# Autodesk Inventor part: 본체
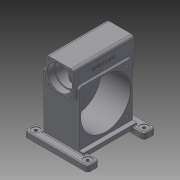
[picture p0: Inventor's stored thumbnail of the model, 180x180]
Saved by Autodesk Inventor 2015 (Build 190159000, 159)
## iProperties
Created: 2025-06
Part Number: 본체
Material: 일반
Document SubType Name: Modeling
Designer: 104
Density: 1 g/cm^3
Appearance: 기본값
Author: 104
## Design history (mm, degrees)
sketch "스케치1"
  geometry: L1 (-93, -103)-(93, -103); L2 (93, -103)-(93, 103); L3 (93, 103)-(-93, 103); L4 (-93, 103)-(-93, -103); L5 (-93, -103)-(93, 103); L6 (93, -103)-(-93, 103); 1 further point
  constraints: 12 end point, 2 midpoint, 2 parallel, 1 horizontal, 1 perpendicular
  dimensions: "d0" = 186 distance of L3.end L2.end; "d1" = 206 distance of L2.end L1.end
extrude "돌출1" new body sketch "스케치1" distance "d2" = 140; taper "d3" = 0 deg
sketch "스케치2"
  geometry: L1 (140, 206)-(125, 206); L2 (125, 206)-(125, 17); L3 (125, 17)-(140, 17); L4 (140, 17)-(140, 206); 1 further point
  constraints: 8 end point, 2 parallel, 1 horizontal, 1 perpendicular
  dimensions: "d4" = 15 distance of L3.end L2.end; "d5" = 189 distance of L2.end L1.end
extrude "돌출2" cut sketch "스케치2" stored distance "d6" = 140; taper "d7" = 0 deg
node "작업 평면1"
sketch "스케치3"
  geometry: L1 (-140, -86)-(-125, -86) reference; L2 (-125, -86)-(-125, 103) reference; L3 (0, 103)-(-125, 103) reference; L4 (0, 103)-(0, -103) reference; L5 (0, -103)-(-140, -103) reference; L6 (-140, -86)-(-140, -103) reference; L7 (-22, 158)-(-118, 158); L8 (-118, 158)-(-118, 62); L9 (-118, 62)-(-22, 62); L10 (-22, 62)-(-22, 158); 3 further points
  constraints: 8 end point, 2 midpoint, 2 parallel, 1 horizontal, 1 perpendicular, 1 vertical alignment
  dimensions: "d9" = 96 distance of L7.start L7.end; "d10" = 96 distance of L7.end L8.end; "d11" = 55 distance between parallel lines of L7 L3
extrude "돌출3" join sketch "스케치3" distance "d12" = 210; taper "d13" = 0 deg
sketch "스케치4"
  geometry: L1 (118, 62)-(22, 62) reference; L2 (118, 158)-(118, 62) reference; C1 r 42.5 at (70, 110); 3 further points
  constraints: 2 midpoint, 1 centre point, 1 horizontal alignment, 1 vertical alignment
  dimensions: "d14" = 85 diameter of C1
extrude "돌출4" cut sketch "스케치4" distance "d15" = 23; taper "d16" = 0 deg
sketch "스케치5"
  geometry: C1 r 42.5 at (0, 0) reference; C2 r 38.5 at (0, 0); 1 further point
  constraints: 1 centre point, 1 coincident
  dimensions: "d17" = 77 diameter of C2
extrude "돌출5" cut sketch "스케치5" stored distance "d18" = 23; taper "d19" = 0 deg
node "작업 평면2"
sketch "스케치7"
  geometry: L1 (158, -13)-(-62, -13); L2 (-62, -13)-(-62, 27); L3 (-62, 27)-(158, 27); L4 (158, 27)-(158, -13); L5 (96, 0)-(0, 0) reference; L6 (158, 223)-(-62, 223); L7 (-62, 223)-(-62, 183); L8 (-62, 183)-(158, 183); L9 (158, 183)-(158, 223); L10 (96, 210)-(0, 210) reference; 5 further points
  constraints: 16 end point, 4 midpoint, 4 parallel, 2 horizontal, 2 perpendicular, 2 vertical alignment
  dimensions: "d26" = 220 distance of L2.end L3.end; "d27" = 40 distance of L1.end L2.end; "d28" = 118 distance from line of L1 point (-22, 105); "d29" = 220 distance of L8.end L7.end; "d30" = 40 distance of L7.end L6.end; "d31" = 118 distance from line of L6 point (-22, 105)
extrude "돌출6" join sketch "스케치7" distance "d32" = 20; taper "d33" = 0 deg
sketch "스케치8"
  geometry: L1 (216, 171)-(216, 211) reference; C1 r 86 at (93, 93); 1 further point
  constraints: 1 centre point, 1 horizontal alignment
  dimensions: "d34" = 172 diameter of C1; "d35" = 123 distance from line of L1 C1.centre
extrude "돌출7" cut sketch "스케치8" distance "d36" = 102; taper "d37" = 0 deg
sketch "스케치9"
  geometry: C1 r 86 at (0, 0) reference; 1 further point
hole "구멍1" sketch "스케치9" at (0, 0) diameter "d38" = 62; stored, may be unused: countersink angle "d42" = 90 deg, drill point angle "d44" = 0 deg; dims "d39" = 6, "d40" = 4, "d41" = 2, "d43" = 16
sketch "스케치10"
  geometry: C1 r 31 at (0, 0) reference; 1 further point
hole "구멍2" sketch "스케치10" at (0, 0) diameter "d45" = 54; stored, may be unused: countersink angle "d49" = 90 deg, drill point angle "d51" = 0 deg; dims "d46" = 6, "d47" = 4, "d48" = 2, "d50" = 3
fillet "모깎기1" dims "d52" = 1
fillet "모깎기2" dims "d53" = 10
sketch "스케치11"
  geometry: L1 (148, 223)-(-52, 223) reference; L2 (-62, -3)-(-62, 17) reference; L3 (-52, 27)-(148, 27) reference; L4 (158, 17)-(158, -3) reference; L5 (148, -13)-(-52, -13) reference; L6 (-42, 7)-(138, 7); L7 (138, 7)-(138, 203); L8 (138, 203)-(-42, 203); L9 (-42, 203)-(-42, 7); L10 (148, -13)-(-52, -13) reference; L11 (48, -13)-(48, 223); A1 r 10 centre (-52, -3) between (-62, -3) and (-52, -13) reference; A2 r 10 centre (148, -3) between (148, -13) and (158, -3) reference; A3 r 10 centre (148, 17) between (158, 17) and (148, 27) reference; A4 r 10 centre (-52, 17) between (-52, 27) and (-62, 17) reference; 4 further points
  constraints: 10 end point, 5 midpoint, 2 parallel, 2 perpendicular, 1 horizontal, 1 horizontal alignment, 1 vertical alignment
  dimensions: "d54" = 180 distance of L8.end L7.end; "d55" = 196 distance of L7.end L6.end
hole "구멍3" sketch "스케치11" at (138, 7), (138, 203), (-42, 7), (-42, 203) diameter "d56" = 11; stored, may be unused: countersink angle "d60" = 90 deg, drill point angle "d62" = 0 deg; dims "d57" = 6, "d58" = 28, "d59" = 2, "d61" = 3
sketch "스케치12"
  geometry: L1 (18, 18)-(168, 18); L2 (168, 18)-(168, 168); L3 (168, 168)-(18, 168); L4 (18, 168)-(18, 18); C1 r 86 at (93, 93) reference; 3 further points
  constraints: 8 end point, 2 midpoint, 2 parallel, 1 horizontal, 1 horizontal alignment, 1 perpendicular, 1 vertical alignment
  dimensions: "d63" = 150 distance of L3.end L2.end; "d64" = 150 distance of L2.end L1.end
hole "구멍4" sketch "스케치12" at (18, 18), (18, 168), (168, 168), (168, 18) diameter "d65" = 6.647; stored, may be unused: countersink angle "d69" = 90 deg, drill point angle "d71" = 118 deg; dims "d66" = 16, "d67" = 28, "d68" = 2, "d70" = 18
sketch "스케치13"
  geometry: L1 (22, 158)-(118, 158) reference; L2 (32, 148)-(108, 148); L3 (108, 148)-(108, 72); L4 (108, 72)-(32, 72); L5 (32, 72)-(32, 148); C1 r 42.5 at (70, 110) reference; 4 further points
  constraints: 8 end point, 3 midpoint, 2 parallel, 1 horizontal, 1 horizontal alignment, 1 perpendicular, 1 vertical alignment
  dimensions: "d72" = 76 distance of L3.end L4.end; "d73" = 76 distance of L2.end L3.end
hole "구멍5" sketch "스케치13" at (108, 148), (32, 148), (32, 72), (108, 72) diameter "d74" = 4.917; stored, may be unused: countersink angle "d78" = 90 deg, drill point angle "d80" = 118 deg; dims "d75" = 12, "d76" = 28, "d77" = 2, "d79" = 14
node "작업 평면3"
fillet "모깎기3" dims "d81" = 3
fillet "모깎기4" dims "d82" = 3
fillet "모깎기5" dims "d83" = 3
fillet "모깎기9" dims "d87" = 1.1
sketch "스케치14"
  geometry: L1 (-10, 210)-(-10, 0) reference; 3 further points
  constraints: 1 horizontal alignment, 1 midpoint, 1 other
  dimensions: "d88" = 30 distance from line of point (20, 105) L1
feature "엠보싱1" sketch "스케치14" dims "d89" = 0.5, "d90" = 0
fillet "모깎기10" dims "d91" = 3
chamfer "모따기1" distance "d92" = 1; stored, may be unused: second distance "d93" = 2, angle "d94" = 45 deg
chamfer "모따기2" distance "d95" = 1; stored, may be unused: second distance "d96" = 2, angle "d97" = 45 deg
fillet "모깎기11" dims "d98" = 3
fillet "모깎기13" dims "d100" = 3
fillet "모깎기14" dims "d101" = 3
chamfer "모따기3" distance "d102" = 1; stored, may be unused: second distance "d103" = 2, angle "d104" = 45 deg
fillet "모깎기15" dims "d105" = 10
fillet "모깎기16" dims "d106" = 3
node "솔리드1"
mirror "대칭1"
mirror "대칭2"
node "투영된 루프1"
node "투영된 루프3"
other parameters: "d8" = -105, "d25" = -271
